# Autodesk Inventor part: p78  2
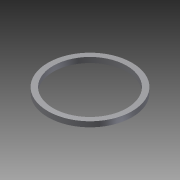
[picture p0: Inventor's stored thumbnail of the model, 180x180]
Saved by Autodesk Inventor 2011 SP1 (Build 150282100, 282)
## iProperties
Created: 2014-02
Part Number: p78  2
Document SubType Name: Modeling
Designer: Administrator
Density: 1 g/cm^3
Author: Administrator
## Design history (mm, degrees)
sketch "草图1"
  geometry: C1 r 40 at (0, 0); 1 further point
  constraints: 1 centre point, 1 coincident
  dimensions: "d0" = 80 diameter of C1
extrude "拉伸1" new body sketch "草图1" distance "d1" = 5; taper "d2" = 0 deg
hole "Hole1" diameter "d5" = 70; stored, may be unused: countersink angle "d9" = 90 deg, drill point angle "d11" = 118 deg; dims "d3" = 10, "d4" = 10, "d6" = 6, "d7" = 4, "d8" = 2, "d10" = 8
node "实体1"
